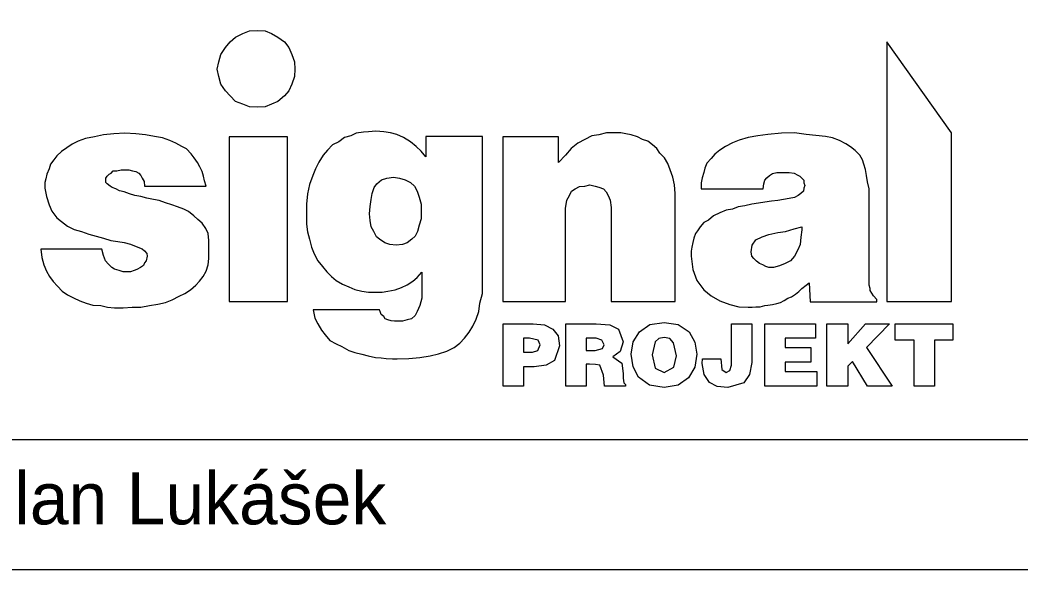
# Model space of a CAD drawing. Extents: x -650084 to -649664, y -1160055 to -1159758.
# Drawn here: x -649740.75 to -649702.37, y -1159954.5 to -1159933.4 of the extents above; entities that cross this region are included whole.
import ezdxf

# ---------------------------------------------------------------- set-up
doc = ezdxf.new("R2010")
doc.units = 0
for name, color, linetype in [('Info o rozpiskách', 7, 'Continuous'), ('popis', 7, 'Continuous'), ('Rozpiska_pole_6', 7, 'Continuous')]:
    doc.layers.add(name, color=color, linetype=linetype)

msp = doc.modelspace()

# ---------------------------------------------------------------- linework, layer by layer
at = {"layer": 'Info o rozpiskách'}
for points in [[(-649731.619, -1159933.803), (-649731.338, -1159933.823), (-649731.098, -1159933.923), (-649730.857, -1159934.063), (-649730.597, -1159934.244), (-649730.437, -1159934.464), (-649730.317, -1159934.725), (-649730.216, -1159935.005), (-649730.197, -1159935.285), (-649730.216, -1159935.566), (-649730.317, -1159935.866), (-649730.437, -1159936.126), (-649730.597, -1159936.307), (-649730.857, -1159936.528), (-649731.098, -1159936.628), (-649731.338, -1159936.728), (-649731.619, -1159936.748), (-649731.94, -1159936.728), (-649732.2, -1159936.628), (-649732.481, -1159936.528), (-649732.681, -1159936.307), (-649732.861, -1159936.126), (-649733.041, -1159935.866), (-649733.122, -1159935.566), (-649733.182, -1159935.285), (-649733.122, -1159935.005), (-649733.041, -1159934.725), (-649732.861, -1159934.464), (-649732.681, -1159934.244), (-649732.481, -1159934.063), (-649732.2, -1159933.923), (-649731.94, -1159933.823), (-649731.619, -1159933.803)], [(-649722.204, -1159945.061), (-649721.062, -1159945.061), (-649720.621, -1159945.101), (-649720.3, -1159945.261), (-649720.1, -1159945.522), (-649720.04, -1159945.902), (-649720.24, -1159946.463), (-649720.561, -1159946.644), (-649721.022, -1159946.704), (-649721.422, -1159946.704), (-649721.422, -1159947.445), (-649722.204, -1159947.445), (-649722.204, -1159945.061)], [(-649719.8, -1159945.061), (-649718.638, -1159945.061), (-649718.117, -1159945.101), (-649717.777, -1159945.261), (-649717.596, -1159945.742), (-649717.716, -1159946.123), (-649717.997, -1159946.323), (-649717.656, -1159946.564), (-649717.596, -1159946.964), (-649717.596, -1159947.145), (-649717.577, -1159947.325), (-649717.516, -1159947.385), (-649717.516, -1159947.445), (-649718.318, -1159947.445), (-649718.358, -1159947.024), (-649718.497, -1159946.644), (-649718.658, -1159946.624), (-649718.899, -1159946.604), (-649719.018, -1159946.604), (-649719.018, -1159947.445), (-649719.8, -1159947.445), (-649719.8, -1159945.061)], [(-649716.034, -1159945.001), (-649715.493, -1159945.081), (-649715.072, -1159945.361), (-649714.852, -1159945.763), (-649714.772, -1159946.223), (-649714.852, -1159946.724), (-649715.092, -1159947.124), (-649715.493, -1159947.405), (-649716.034, -1159947.505), (-649716.594, -1159947.405), (-649717.015, -1159947.104), (-649717.215, -1159946.704), (-649717.296, -1159946.223), (-649717.215, -1159945.742), (-649716.975, -1159945.361), (-649716.575, -1159945.081), (-649716.034, -1159945.001)], [(-649713.45, -1159945.061), (-649712.669, -1159945.061), (-649712.669, -1159946.544), (-649712.749, -1159947.004), (-649712.969, -1159947.325), (-649713.591, -1159947.505), (-649713.991, -1159947.465), (-649714.291, -1159947.305), (-649714.492, -1159947.004), (-649714.572, -1159946.583), (-649714.552, -1159946.404), (-649713.851, -1159946.404), (-649713.81, -1159946.804), (-649713.65, -1159946.924), (-649713.51, -1159946.844), (-649713.45, -1159946.644), (-649713.45, -1159945.061)], [(-649712.168, -1159945.061), (-649710.225, -1159945.061), (-649710.225, -1159945.602), (-649711.387, -1159945.602), (-649711.387, -1159945.963), (-649710.406, -1159945.963), (-649710.406, -1159946.523), (-649711.387, -1159946.523), (-649711.387, -1159946.884), (-649710.165, -1159946.884), (-649710.165, -1159947.445), (-649712.168, -1159947.445), (-649712.168, -1159945.061)], [(-649709.784, -1159945.061), (-649708.983, -1159945.061), (-649708.983, -1159945.823), (-649708.302, -1159945.061), (-649707.381, -1159945.061), (-649708.262, -1159945.963), (-649707.28, -1159947.445), (-649708.222, -1159947.445), (-649708.803, -1159946.504), (-649708.983, -1159946.683), (-649708.983, -1159947.445), (-649709.784, -1159947.445), (-649709.784, -1159945.061)], [(-649707.16, -1159945.061), (-649704.956, -1159945.061), (-649704.956, -1159945.682), (-649705.658, -1159945.682), (-649705.658, -1159947.445), (-649706.439, -1159947.445), (-649706.439, -1159945.682), (-649707.16, -1159945.682), (-649707.16, -1159945.061)], [(-649721.422, -1159945.602), (-649721.422, -1159946.143), (-649721.082, -1159946.143), (-649720.881, -1159946.083), (-649720.781, -1159945.863), (-649720.862, -1159945.682), (-649721.202, -1159945.602), (-649721.422, -1159945.602)], [(-649719.018, -1159945.602), (-649719.018, -1159946.083), (-649718.678, -1159946.083), (-649718.397, -1159946.003), (-649718.337, -1159945.863), (-649718.418, -1159945.682), (-649718.638, -1159945.602), (-649719.018, -1159945.602)], [(-649716.034, -1159945.582), (-649716.234, -1159945.622), (-649716.374, -1159945.742), (-649716.494, -1159946.243), (-649716.374, -1159946.764), (-649716.034, -1159946.924), (-649715.653, -1159946.724), (-649715.553, -1159946.283), (-649715.673, -1159945.782), (-649715.813, -1159945.622), (-649716.034, -1159945.582)]]:
    msp.add_lwpolyline(points, dxfattribs=at)
at = {"layer": 'popis'}
for points in [[(-649707.481, -1159934.244), (-649707.481, -1159944.2), (-649704.997, -1159944.2), (-649704.997, -1159937.729), (-649707.481, -1159934.244)], [(-649735.966, -1159939.773), (-649733.603, -1159939.773), (-649733.662, -1159939.572), (-649733.703, -1159939.392), (-649733.763, -1159939.212), (-649733.842, -1159939.031), (-649733.943, -1159938.871), (-649734.063, -1159938.691), (-649734.183, -1159938.531), (-649734.363, -1159938.35), (-649734.544, -1159938.25), (-649734.764, -1159938.13), (-649735.004, -1159938.029), (-649735.285, -1159937.929), (-649735.585, -1159937.869), (-649735.926, -1159937.81), (-649736.307, -1159937.769), (-649736.727, -1159937.75), (-649737.148, -1159937.769), (-649737.548, -1159937.81), (-649737.889, -1159937.889), (-649738.229, -1159937.95), (-649738.51, -1159938.05), (-649738.751, -1159938.17), (-649738.951, -1159938.31), (-649739.151, -1159938.45), (-649739.332, -1159938.611), (-649739.451, -1159938.771), (-649739.572, -1159938.931), (-649739.632, -1159939.111), (-649739.712, -1159939.312), (-649739.752, -1159939.492), (-649739.792, -1159939.632), (-649739.792, -1159939.853), (-649739.732, -1159940.173), (-649739.632, -1159940.494), (-649739.532, -1159940.734), (-649739.332, -1159940.995), (-649739.151, -1159941.135), (-649738.931, -1159941.315), (-649738.67, -1159941.435), (-649738.39, -1159941.516), (-649738.11, -1159941.616), (-649737.829, -1159941.695), (-649737.548, -1159941.776), (-649737.268, -1159941.856), (-649736.988, -1159941.896), (-649736.747, -1159941.936), (-649736.507, -1159941.997), (-649736.286, -1159942.097), (-649736.066, -1159942.176), (-649735.966, -1159942.257), (-649735.886, -1159942.357), (-649735.866, -1159942.457), (-649735.906, -1159942.637), (-649735.966, -1159942.717), (-649736.006, -1159942.817), (-649736.126, -1159942.898), (-649736.266, -1159942.978), (-649736.367, -1159943.018), (-649736.507, -1159943.058), (-649736.647, -1159943.058), (-649736.788, -1159943.058), (-649736.948, -1159943.018), (-649737.128, -1159942.958), (-649737.228, -1159942.898), (-649737.369, -1159942.757), (-649737.469, -1159942.637), (-649737.548, -1159942.437), (-649737.609, -1159942.197), (-649739.953, -1159942.197), (-649739.913, -1159942.517), (-649739.832, -1159942.798), (-649739.732, -1159943.038), (-649739.612, -1159943.238), (-649739.472, -1159943.439), (-649739.311, -1159943.619), (-649739.131, -1159943.799), (-649738.931, -1159943.939), (-649738.691, -1159944.06), (-649738.45, -1159944.18), (-649738.21, -1159944.26), (-649737.95, -1159944.34), (-649737.648, -1159944.36), (-649737.388, -1159944.42), (-649737.128, -1159944.441), (-649736.788, -1159944.441), (-649736.447, -1159944.42), (-649736.106, -1159944.42), (-649735.785, -1159944.36), (-649735.465, -1159944.3), (-649735.165, -1159944.239), (-649734.904, -1159944.139), (-649734.644, -1159944), (-649734.423, -1159943.899), (-649734.203, -1159943.759), (-649734.003, -1159943.579), (-649733.863, -1159943.419), (-649733.722, -1159943.238), (-649733.603, -1159943.038), (-649733.522, -1159942.798), (-649733.502, -1159942.557), (-649733.502, -1159942.317), (-649733.502, -1159942.257), (-649733.502, -1159942.197), (-649733.502, -1159942.136), (-649733.502, -1159942.076), (-649733.502, -1159941.997), (-649733.502, -1159941.936), (-649733.502, -1159941.896), (-649733.502, -1159941.856), (-649733.522, -1159941.595), (-649733.622, -1159941.395), (-649733.763, -1159941.195), (-649733.923, -1159941.054), (-649734.083, -1159940.914), (-649734.283, -1159940.754), (-649734.463, -1159940.654), (-649734.704, -1159940.574), (-649734.925, -1159940.494), (-649735.165, -1159940.414), (-649735.405, -1159940.333), (-649735.625, -1159940.294), (-649735.886, -1159940.233), (-649736.106, -1159940.173), (-649736.347, -1159940.133), (-649736.547, -1159940.073), (-649736.747, -1159939.993), (-649736.928, -1159939.953), (-649737.067, -1159939.873), (-649737.208, -1159939.833), (-649737.288, -1159939.773), (-649737.408, -1159939.692), (-649737.448, -1159939.632), (-649737.448, -1159939.553), (-649737.448, -1159939.472), (-649737.408, -1159939.392), (-649737.328, -1159939.312), (-649737.248, -1159939.272), (-649737.168, -1159939.192), (-649737.028, -1159939.192), (-649736.867, -1159939.151), (-649736.727, -1159939.151), (-649736.567, -1159939.151), (-649736.426, -1159939.192), (-649736.307, -1159939.212), (-649736.186, -1159939.272), (-649736.106, -1159939.372), (-649736.066, -1159939.472), (-649735.986, -1159939.592), (-649735.966, -1159939.773)], [(-649732.72, -1159937.889), (-649732.72, -1159944.2), (-649730.477, -1159944.2), (-649730.477, -1159937.889), (-649732.72, -1159937.889)], [(-649725.169, -1159937.869), (-649725.169, -1159938.651), (-649725.349, -1159938.431), (-649725.549, -1159938.25), (-649725.769, -1159938.07), (-649726.03, -1159937.91), (-649726.29, -1159937.789), (-649726.531, -1159937.729), (-649726.791, -1159937.689), (-649727.091, -1159937.669), (-649727.372, -1159937.689), (-649727.572, -1159937.709), (-649727.853, -1159937.75), (-649728.053, -1159937.85), (-649728.294, -1159937.91), (-649728.514, -1159938.07), (-649728.754, -1159938.19), (-649728.954, -1159938.391), (-649729.115, -1159938.591), (-649729.275, -1159938.851), (-649729.415, -1159939.111), (-649729.516, -1159939.372), (-649729.635, -1159939.713), (-649729.716, -1159940.073), (-649729.756, -1159940.473), (-649729.756, -1159940.894), (-649729.756, -1159941.235), (-649729.716, -1159941.535), (-649729.635, -1159941.816), (-649729.556, -1159942.116), (-649729.456, -1159942.377), (-649729.315, -1159942.637), (-649729.135, -1159942.857), (-649728.975, -1159943.058), (-649728.794, -1159943.238), (-649728.614, -1159943.398), (-649728.374, -1159943.539), (-649728.134, -1159943.639), (-649727.893, -1159943.739), (-649727.632, -1159943.799), (-649727.372, -1159943.839), (-649727.091, -1159943.839), (-649726.851, -1159943.839), (-649726.631, -1159943.799), (-649726.35, -1159943.759), (-649726.11, -1159943.659), (-649725.89, -1159943.559), (-649725.669, -1159943.419), (-649725.509, -1159943.278), (-649725.329, -1159943.078), (-649725.329, -1159943.659), (-649725.329, -1159944.079), (-649725.409, -1159944.36), (-649725.509, -1159944.58), (-649725.59, -1159944.741), (-649725.729, -1159944.861), (-649725.89, -1159944.901), (-649726.07, -1159944.961), (-649726.27, -1159944.961), (-649726.371, -1159944.961), (-649726.51, -1159944.941), (-649726.631, -1159944.901), (-649726.731, -1159944.861), (-649726.791, -1159944.781), (-649726.891, -1159944.701), (-649726.912, -1159944.62), (-649726.951, -1159944.52), (-649729.495, -1159944.52), (-649729.435, -1159944.841), (-649729.315, -1159945.061), (-649729.175, -1159945.301), (-649729.035, -1159945.482), (-649728.854, -1159945.702), (-649728.614, -1159945.823), (-649728.394, -1159945.923), (-649728.134, -1159946.083), (-649727.893, -1159946.163), (-649727.632, -1159946.223), (-649727.392, -1159946.283), (-649727.112, -1159946.343), (-649726.891, -1159946.363), (-649726.691, -1159946.383), (-649726.45, -1159946.404), (-649726.27, -1159946.404), (-649725.829, -1159946.383), (-649725.409, -1159946.343), (-649725.008, -1159946.283), (-649724.688, -1159946.203), (-649724.368, -1159946.103), (-649724.087, -1159945.963), (-649723.866, -1159945.802), (-649723.686, -1159945.602), (-649723.506, -1159945.382), (-649723.366, -1159945.141), (-649723.246, -1159944.881), (-649723.146, -1159944.58), (-649723.105, -1159944.26), (-649723.005, -1159943.899), (-649723.005, -1159943.519), (-649723.005, -1159943.078), (-649723.005, -1159937.869), (-649725.169, -1159937.869)], [(-649722.224, -1159937.889), (-649722.224, -1159944.2), (-649719.819, -1159944.2), (-649719.819, -1159940.975), (-649719.819, -1159940.634), (-649719.76, -1159940.313), (-649719.659, -1159940.133), (-649719.58, -1159939.973), (-649719.439, -1159939.873), (-649719.279, -1159939.792), (-649719.078, -1159939.773), (-649718.878, -1159939.732), (-649718.678, -1159939.773), (-649718.538, -1159939.813), (-649718.358, -1159939.873), (-649718.257, -1159939.993), (-649718.177, -1159940.133), (-649718.097, -1159940.313), (-649718.057, -1159940.594), (-649718.057, -1159940.875), (-649718.057, -1159944.2), (-649715.613, -1159944.2), (-649715.613, -1159940.394), (-649715.613, -1159940.053), (-649715.633, -1159939.732), (-649715.693, -1159939.432), (-649715.793, -1159939.151), (-649715.893, -1159938.911), (-649716.014, -1159938.691), (-649716.194, -1159938.51), (-649716.314, -1159938.33), (-649716.474, -1159938.19), (-649716.655, -1159938.05), (-649716.855, -1159937.99), (-649717.055, -1159937.889), (-649717.296, -1159937.81), (-649717.496, -1159937.769), (-649717.696, -1159937.729), (-649717.937, -1159937.729), (-649718.237, -1159937.729), (-649718.538, -1159937.81), (-649718.799, -1159937.85), (-649719.078, -1159937.99), (-649719.339, -1159938.13), (-649719.6, -1159938.33), (-649719.819, -1159938.591), (-649720.08, -1159938.871), (-649720.08, -1159937.889), (-649722.224, -1159937.889)], [(-649714.612, -1159939.873), (-649712.228, -1159939.873), (-649712.209, -1159939.692), (-649712.168, -1159939.553), (-649712.088, -1159939.452), (-649711.988, -1159939.372), (-649711.868, -1159939.292), (-649711.707, -1159939.251), (-649711.568, -1159939.251), (-649711.407, -1159939.251), (-649711.227, -1159939.251), (-649711.046, -1159939.272), (-649710.906, -1159939.352), (-649710.826, -1159939.392), (-649710.746, -1159939.472), (-649710.666, -1159939.553), (-649710.666, -1159939.653), (-649710.625, -1159939.753), (-649710.666, -1159939.853), (-649710.685, -1159939.973), (-649710.786, -1159940.053), (-649710.886, -1159940.133), (-649711.026, -1159940.213), (-649711.227, -1159940.254), (-649711.447, -1159940.294), (-649711.668, -1159940.333), (-649711.908, -1159940.354), (-649712.168, -1159940.394), (-649712.409, -1159940.434), (-649712.669, -1159940.473), (-649712.929, -1159940.534), (-649713.19, -1159940.574), (-649713.41, -1159940.654), (-649713.65, -1159940.694), (-649713.891, -1159940.794), (-649714.131, -1159940.914), (-649714.332, -1159941.075), (-649714.512, -1159941.175), (-649714.652, -1159941.335), (-649714.752, -1159941.495), (-649714.831, -1159941.595), (-649714.892, -1159941.776), (-649714.932, -1159941.936), (-649714.972, -1159942.116), (-649714.992, -1159942.276), (-649714.992, -1159942.457), (-649714.932, -1159942.978), (-649714.772, -1159943.398), (-649714.512, -1159943.759), (-649714.231, -1159943.979), (-649713.891, -1159944.18), (-649713.51, -1159944.32), (-649713.17, -1159944.4), (-649712.809, -1159944.42), (-649712.649, -1159944.42), (-649712.509, -1159944.4), (-649712.349, -1159944.4), (-649712.168, -1159944.36), (-649712.048, -1159944.34), (-649711.868, -1159944.32), (-649711.707, -1159944.28), (-649711.568, -1159944.239), (-649711.427, -1159944.16), (-649711.287, -1159944.079), (-649711.147, -1159944.02), (-649710.987, -1159943.919), (-649710.866, -1159943.819), (-649710.746, -1159943.699), (-649710.585, -1159943.579), (-649710.465, -1159943.479), (-649710.425, -1159944.22), (-649707.862, -1159944.22), (-649707.862, -1159944.12), (-649708.002, -1159943.979), (-649708.062, -1159943.879), (-649708.122, -1159943.779), (-649708.122, -1159943.699), (-649708.162, -1159943.579), (-649708.162, -1159943.498), (-649708.162, -1159943.379), (-649708.162, -1159943.219), (-649708.162, -1159940.133), (-649708.162, -1159939.873), (-649708.222, -1159939.613), (-649708.262, -1159939.372), (-649708.302, -1159939.132), (-649708.362, -1159938.931), (-649708.422, -1159938.771), (-649708.522, -1159938.591), (-649708.703, -1159938.41), (-649708.883, -1159938.27), (-649709.063, -1159938.15), (-649709.303, -1159938.029), (-649709.564, -1159937.929), (-649709.844, -1159937.869), (-649710.205, -1159937.829), (-649710.585, -1159937.789), (-649711.026, -1159937.729), (-649711.527, -1159937.75), (-649712.048, -1159937.789), (-649712.429, -1159937.85), (-649712.809, -1159937.91), (-649713.15, -1159938.01), (-649713.41, -1159938.11), (-649713.671, -1159938.25), (-649713.891, -1159938.391), (-649714.091, -1159938.551), (-649714.231, -1159938.711), (-649714.392, -1159938.891), (-649714.472, -1159939.091), (-649714.512, -1159939.251), (-649714.572, -1159939.452), (-649714.612, -1159939.653), (-649714.612, -1159939.873)], [(-649726.41, -1159939.432), (-649726.19, -1159939.472), (-649725.97, -1159939.532), (-649725.769, -1159939.632), (-649725.609, -1159939.773), (-649725.509, -1159939.973), (-649725.429, -1159940.194), (-649725.349, -1159940.473), (-649725.349, -1159940.775), (-649725.349, -1159941.035), (-649725.429, -1159941.275), (-649725.489, -1159941.516), (-649725.59, -1159941.695), (-649725.709, -1159941.816), (-649725.89, -1159941.956), (-649726.07, -1159942.016), (-649726.31, -1159942.036), (-649726.551, -1159942.016), (-649726.751, -1159941.956), (-649726.951, -1159941.816), (-649727.072, -1159941.716), (-649727.172, -1159941.516), (-649727.272, -1159941.335), (-649727.312, -1159941.095), (-649727.332, -1159940.835), (-649727.312, -1159940.554), (-649727.272, -1159940.294), (-649727.232, -1159940.053), (-649727.152, -1159939.833), (-649727.051, -1159939.692), (-649726.871, -1159939.532), (-649726.671, -1159939.472), (-649726.41, -1159939.432)], [(-649710.746, -1159941.335), (-649710.746, -1159941.355), (-649710.746, -1159941.416), (-649710.746, -1159941.455), (-649710.786, -1159941.736), (-649710.806, -1159942.016), (-649710.906, -1159942.217), (-649711.026, -1159942.457), (-649711.187, -1159942.637), (-649711.387, -1159942.738), (-649711.607, -1159942.838), (-649711.828, -1159942.898), (-649712.008, -1159942.898), (-649712.128, -1159942.857), (-649712.248, -1159942.798), (-649712.369, -1159942.738), (-649712.488, -1159942.657), (-649712.589, -1159942.557), (-649712.669, -1159942.457), (-649712.689, -1159942.297), (-649712.649, -1159942.036), (-649712.509, -1159941.836), (-649712.268, -1159941.716), (-649712.008, -1159941.635), (-649711.668, -1159941.556), (-649711.367, -1159941.516), (-649711.046, -1159941.416), (-649710.746, -1159941.335)]]:
    msp.add_lwpolyline(points, dxfattribs=at)
at = {"layer": 'Rozpiska_pole_6'}
msp.add_line((-649854, -1159949.5), (-649684, -1159949.5), dxfattribs=at)
msp.add_lwpolyline([(-649854, -1159914.5), (-649684, -1159914.5), (-649684, -1159954.5), (-649854, -1159954.5)], close=True, dxfattribs=at)

# ---------------------------------------------------------------- texts
msp.add_text('Ing. Milan Lukášek', height=2, dxfattribs=at).set_placement((-649748.992, -1159952.75))

doc.saveas('drawing.dxf')
